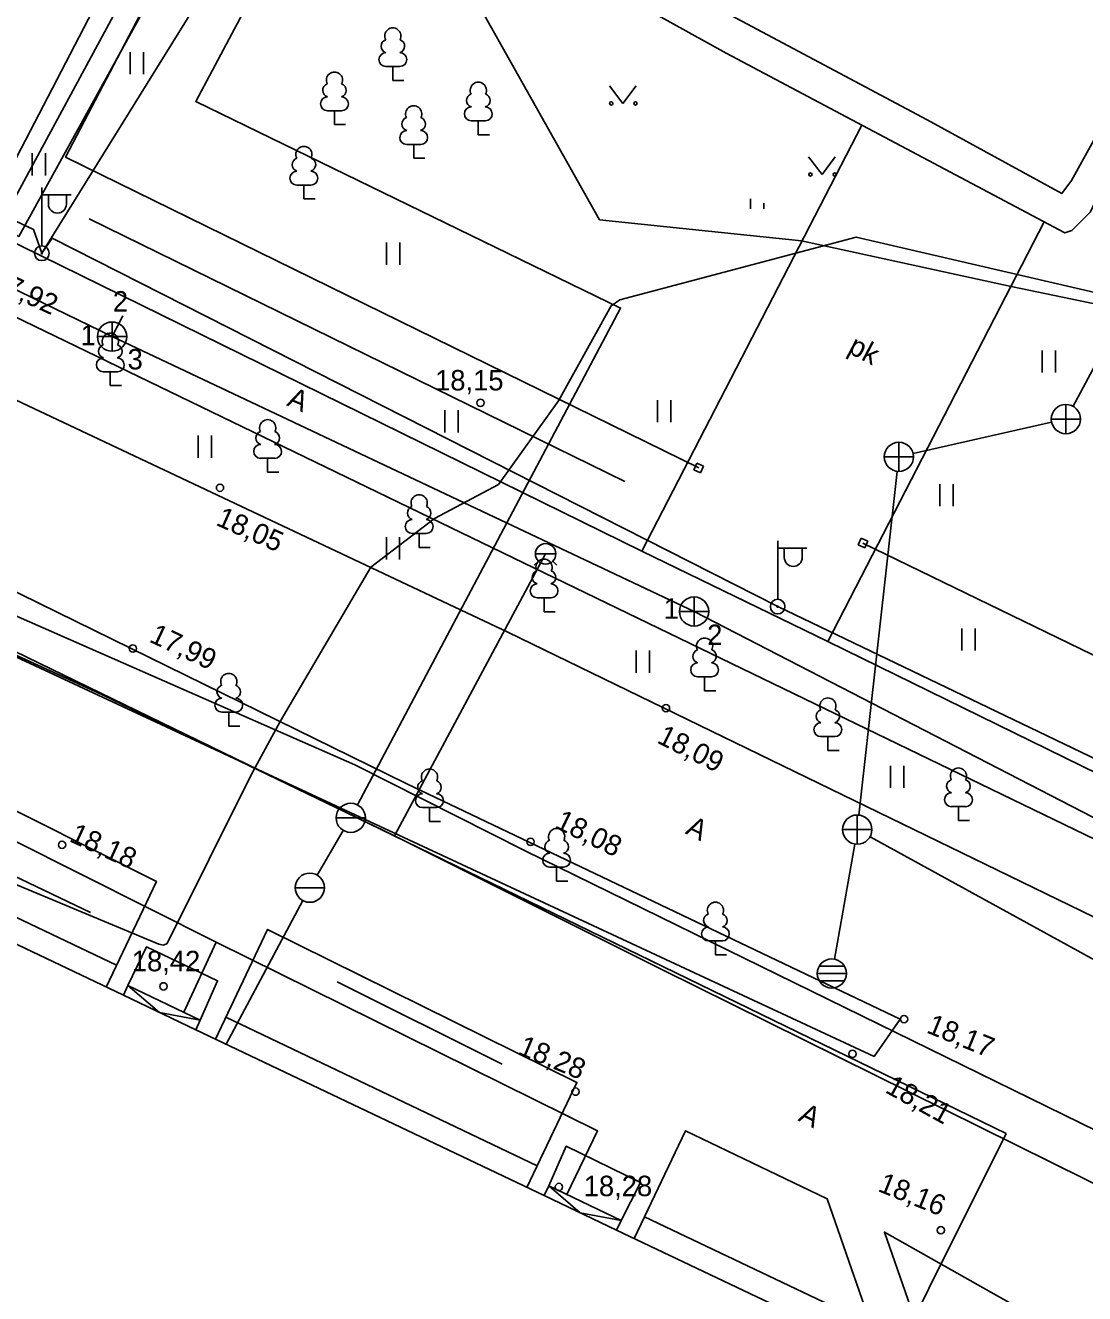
# Model space of a CAD drawing. Extents: x 713540 to 713867, y 6589774 to 6590061.
# Drawn here: x 713801.99 to 713838.21, y 6589841.34 to 6589884.71 of the extents above; entities that cross this region are included whole.
import ezdxf

# ---------------------------------------------------------------- set-up
doc = ezdxf.new("R2010")
doc.units = 0
for name, color, linetype in [('AED', 7, 'Continuous'), ('HALJASTUS', 7, 'Continuous'), ('HOONE', 7, 'Continuous'), ('HOONEDET', 7, 'Continuous'), ('KKAEV', 7, 'Continuous'), ('KORGUS', 7, 'Continuous'), ('KPKAABEL', 7, 'Continuous'), ('KTRASS', 7, 'Continuous'), ('MPKAABEL', 7, 'Continuous'), ('POST', 7, 'Continuous'), ('PUU', 7, 'Continuous'), ('SITRASS', 7, 'Continuous'), ('SKKAEV', 7, 'Continuous'), ('SKTRASS', 7, 'Continuous'), ('TEE', 7, 'Continuous'), ('TORU NR', 7, 'Continuous'), ('VKAEV', 7, 'Continuous'), ('VTRASS', 7, 'Continuous'), ('Слой 1', 7, 'Continuous')]:
    doc.layers.add(name, color=color, linetype=linetype)

msp = doc.modelspace()

# ---------------------------------------------------------------- linework, layer by layer
at = {"layer": 'AED'}
for p, q in [((713824.958, 6589869.743), (713824.853, 6589869.516)), ((713824.958, 6589869.743), (713825.185, 6589869.638)), ((713825.185, 6589869.638), (713825.08, 6589869.411)), ((713824.853, 6589869.516), (713825.08, 6589869.411)), ((713830.468, 6589866.947), (713830.573, 6589867.174)), ((713830.8, 6589867.069), (713830.573, 6589867.174)), ((713830.695, 6589866.842), (713830.8, 6589867.069)), ((713830.695, 6589866.842), (713830.468, 6589866.947))]:
    msp.add_line(p, q, dxfattribs=at)
for points in [[(713825.019, 6589869.577), (713803.37, 6589880.207), (713807.952, 6589888.966), (713812.34, 6589898.14), (713812.86, 6589897.85)], [(713830.634, 6589867.008), (713866.671, 6589849.512)]]:
    msp.add_lwpolyline(points, dxfattribs=at)
at = {"layer": 'HALJASTUS'}
for p, q in [((713805.579, 6589883.797), (713805.579, 6589883.036)), ((713806.034, 6589883.797), (713806.034, 6589883.036)), ((713821.967, 6589882.647), (713822.43, 6589882.04)), ((713822.43, 6589882.04), (713822.876, 6589882.647)), ((713802.23, 6589880.34), (713802.23, 6589879.579)), ((713802.685, 6589880.34), (713802.685, 6589879.579)), ((713828.777, 6589880.217), (713829.24, 6589879.61)), ((713829.24, 6589879.61), (713829.686, 6589880.217)), ((713826.793, 6589878.783), (713826.793, 6589878.44)), ((713827.248, 6589878.625), (713827.248, 6589878.44)), ((713814.347, 6589877.279), (713814.347, 6589876.518)), ((713814.802, 6589877.279), (713814.802, 6589876.518)), ((713836.767, 6589873.595), (713836.767, 6589872.834)), ((713837.222, 6589873.595), (713837.222, 6589872.834)), ((713823.612, 6589871.898), (713823.612, 6589871.137)), ((713824.067, 6589871.898), (713824.067, 6589871.137)), ((713816.34, 6589871.548), (713816.34, 6589870.787)), ((713816.795, 6589871.548), (713816.795, 6589870.787)), ((713807.909, 6589870.683), (713807.909, 6589869.922)), ((713808.364, 6589870.683), (713808.364, 6589869.922)), ((713833.26, 6589869.025), (713833.26, 6589868.264)), ((713833.715, 6589869.025), (713833.715, 6589868.264)), ((713814.338, 6589867.206), (713814.338, 6589866.445)), ((713814.793, 6589867.206), (713814.793, 6589866.445)), ((713834.016, 6589864.091), (713834.016, 6589863.33)), ((713834.471, 6589864.091), (713834.471, 6589863.33)), ((713822.88, 6589863.334), (713822.88, 6589862.572)), ((713823.335, 6589863.334), (713823.335, 6589862.572)), ((713831.572, 6589859.394), (713831.572, 6589858.633)), ((713832.027, 6589859.394), (713832.027, 6589858.633))]:
    msp.add_line(p, q, dxfattribs=at)
for points in [[(713822.494, 6589869.115), (713804.176, 6589878.091)], [(713795.759, 6589858.426), (713804.223, 6589854.37)], [(713812.651, 6589852), (713818.299, 6589849.187)]]:
    msp.add_lwpolyline(points, dxfattribs=at)
for centre in [(713822.029, 6589882.04), (713822.858, 6589882.04), (713828.839, 6589879.61), (713829.668, 6589879.61)]:
    msp.add_circle(centre, 0.055, dxfattribs=at)
at = {"layer": 'HOONE'}
for points in [[(713856.15, 6589912.28), (713845.91, 6589894.13), (713837.77, 6589879.4), (713837.43, 6589878.96), (713832.83, 6589881.48), (713819.45, 6589888.61), (713819.6, 6589888.94), (713824.63, 6589897.88), (713832.94, 6589912.52), (713838.13, 6589921.78), (713838.47, 6589921.97), (713856.15, 6589912.28)], [(713764.759, 6589857.466), (713770.044, 6589868.594), (713770.394, 6589868.428), (713770.304, 6589868.238), (713776.426, 6589865.322), (713776.583, 6589865.651), (713779.057, 6589864.471), (713778.901, 6589864.143), (713790.849, 6589858.452), (713791.006, 6589858.781), (713793.48, 6589857.601), (713793.324, 6589857.274), (713805.345, 6589851.548), (713805.502, 6589851.877), (713807.976, 6589850.697), (713807.82, 6589850.369), (713819.733, 6589844.695), (713819.889, 6589845.024), (713822.363, 6589843.844), (713822.207, 6589843.517), (713828.374, 6589840.579)], [(713801.581, 6589856.848), (713808.521, 6589853.357), (713821.559, 6589846.908), (713820.508, 6589844.729)], [(713807.976, 6589850.697), (713808.57, 6589852.039), (713806.132, 6589853.2), (713805.502, 6589851.877)], [(713807.415, 6589850.964), (713808.524, 6589853.356)], [(713819.889, 6589845.024), (713820.489, 6589846.381), (713823.032, 6589845.14), (713822.363, 6589843.844)]]:
    msp.add_lwpolyline(points, dxfattribs=at)
at = {"layer": 'HOONEDET'}
for p, q in [((713806.583, 6589850.959), (713805.502, 6589851.877)), ((713807.82, 6589850.369), (713805.345, 6589851.548)), ((713807.976, 6589850.697), (713806.583, 6589850.959)), ((713820.97, 6589844.106), (713819.889, 6589845.024)), ((713822.207, 6589843.517), (713819.733, 6589844.695)), ((713822.363, 6589843.844), (713820.97, 6589844.106))]:
    msp.add_line(p, q, dxfattribs=at)
for points in [[(713824.74, 6589899.73), (713818.11, 6589888.07), (713818.2, 6589888.07), (713825.96, 6589883.76), (713837.54, 6589877.61), (713837.78, 6589877.7), (713838.41, 6589878.33), (713840.01, 6589881.77)], [(713829.99, 6589840.716), (713823.163, 6589843.969)]]:
    msp.add_lwpolyline(points, dxfattribs=at)
at = {"layer": 'KKAEV'}
for p, q in [((713804.959, 6589873.565), (713804.959, 6589874.565)), ((713804.459, 6589874.065), (713805.459, 6589874.065)), ((713837.573, 6589870.746), (713837.573, 6589871.746)), ((713837.073, 6589871.246), (713838.073, 6589871.246)), ((713831.863, 6589869.456), (713831.863, 6589870.456)), ((713831.363, 6589869.956), (713832.363, 6589869.956)), ((713824.862, 6589864.167), (713824.862, 6589865.167)), ((713824.362, 6589864.667), (713825.362, 6589864.667)), ((713830.44, 6589856.708), (713830.44, 6589857.708)), ((713829.94, 6589857.208), (713830.94, 6589857.208))]:
    msp.add_line(p, q, dxfattribs=at)
for centre in [(713804.959, 6589874.065), (713837.573, 6589871.246), (713831.863, 6589869.956), (713824.862, 6589864.667), (713830.44, 6589857.208)]:
    msp.add_circle(centre, 0.5, dxfattribs=at)
at = {"layer": 'KORGUS'}
for centre in [(713817.56, 6589871.8), (713808.65, 6589868.9), (713805.67, 6589863.4), (713823.9, 6589861.36), (713803.25, 6589856.69), (713819.27, 6589856.79), (713806.72, 6589851.85), (713832.04, 6589850.73), (713830.28, 6589849.54), (713820.81, 6589848.25), (713820.24, 6589844.99), (713833.3, 6589843.51)]:
    msp.add_circle(centre, 0.125, dxfattribs=at)
at = {"layer": 'KPKAABEL'}
msp.add_lwpolyline([(713798.55, 6589856.631), (713806.554, 6589853.297), (713806.72, 6589853.255), (713806.842, 6589853.316), (713809.704, 6589859.058), (713810.708, 6589860.907), (713813.804, 6589866.184), (713815.987, 6589867.852), (713818.176, 6589869.014), (713820.222, 6589871.87), (713822.023, 6589875.121), (713822.324, 6589875.322), (713830.403, 6589877.468), (713854.54, 6589871.87), (713866.671, 6589869.213)], dxfattribs=at)
at = {"layer": 'KTRASS'}
for p, q in [((713795.486, 6589878.673), (713804.959, 6589874.065)), ((713804.959, 6589874.065), (713805.323, 6589874.782)), ((713804.959, 6589874.065), (713824.862, 6589864.667)), ((713824.862, 6589864.667), (713862.109, 6589845.451))]:
    msp.add_line(p, q, dxfattribs=at)
at = {"layer": 'MPKAABEL'}
for points in [[(713694.011, 6589938.961), (713720.287, 6589922.261), (713729.28, 6589921.07), (713735.396, 6589911.684), (713736.91, 6589909.36), (713749.796, 6589902.534), (713750.086, 6589902.788), (713778.179, 6589889.116), (713778.272, 6589888.686), (713778.52, 6589888.95), (713802.27, 6589877.73), (713802.558, 6589876.915), (713802.91, 6589877.43), (713827.719, 6589864.835), (713849.02, 6589854.61), (713849.184, 6589854.353), (713849.72, 6589854.26), (713866.671, 6589846.028)], [(713866.671, 6589870.418), (713866.215, 6589870.524), (713859.51, 6589871.028), (713844.257, 6589874.001), (713835.7, 6589875.783), (713828.536, 6589877.344), (713821.631, 6589878.061), (713816.967, 6589886.362), (713816.359, 6589889.318), (713817.008, 6589896.566), (713814.12, 6589901.017)], [(713802.558, 6589876.915), (713807.651, 6589885.123), (713809.238, 6589888.304)]]:
    msp.add_lwpolyline(points, dxfattribs=at)
at = {"layer": 'POST'}
for p, q in [((713802.558, 6589877.165), (713802.558, 6589879.165)), ((713802.558, 6589878.915), (713803.558, 6589878.915)), ((713802.785, 6589878.594), (713802.785, 6589878.915)), ((713803.398, 6589878.594), (713803.398, 6589878.915)), ((713827.719, 6589865.085), (713827.719, 6589867.085)), ((713827.719, 6589866.835), (713828.719, 6589866.835)), ((713827.946, 6589866.514), (713827.946, 6589866.835)), ((713828.558, 6589866.514), (713828.558, 6589866.835))]:
    msp.add_line(p, q, dxfattribs=at)
for centre, radius in [((713802.558, 6589876.915), 0.25), ((713802.558, 6589876.915), 0.0234), ((713827.719, 6589864.835), 0.25), ((713827.719, 6589864.835), 0.0234)]:
    msp.add_circle(centre, radius, dxfattribs=at)
for centre in [(713803.091, 6589878.594), (713828.252, 6589866.514)]:
    msp.add_arc(centre, 0.306, 180, 0, dxfattribs=at)
at = {"layer": 'PUU'}
for p, q in [((713814.801, 6589883.301), (713814.321, 6589883.301)), ((713814.561, 6589882.826), (713814.561, 6589883.301)), ((713814.941, 6589882.826), (713814.561, 6589882.826)), ((713812.804, 6589881.79), (713812.324, 6589881.79)), ((713812.564, 6589881.315), (713812.564, 6589881.79)), ((713812.944, 6589881.315), (713812.564, 6589881.315)), ((713817.723, 6589881.444), (713817.243, 6589881.444)), ((713817.483, 6589880.969), (713817.483, 6589881.444)), ((713817.863, 6589880.969), (713817.483, 6589880.969)), ((713815.513, 6589880.638), (713815.033, 6589880.638)), ((713815.273, 6589880.163), (713815.273, 6589880.638)), ((713815.653, 6589880.163), (713815.273, 6589880.163)), ((713811.759, 6589879.247), (713811.279, 6589879.247)), ((713811.519, 6589878.772), (713811.519, 6589879.247)), ((713811.899, 6589878.772), (713811.519, 6589878.772)), ((713805.14, 6589872.865), (713804.66, 6589872.865)), ((713804.9, 6589872.39), (713804.9, 6589872.865)), ((713805.28, 6589872.39), (713804.9, 6589872.39)), ((713810.52, 6589869.905), (713810.04, 6589869.905)), ((713810.28, 6589869.43), (713810.28, 6589869.905)), ((713810.66, 6589869.43), (713810.28, 6589869.43)), ((713815.7, 6589867.335), (713815.22, 6589867.335)), ((713815.46, 6589866.86), (713815.46, 6589867.335)), ((713815.84, 6589866.86), (713815.46, 6589866.86)), ((713819.97, 6589865.135), (713819.49, 6589865.135)), ((713819.73, 6589864.66), (713819.73, 6589865.135)), ((713820.11, 6589864.66), (713819.73, 6589864.66)), ((713825.46, 6589862.435), (713824.98, 6589862.435)), ((713825.22, 6589861.96), (713825.22, 6589862.435)), ((713825.6, 6589861.96), (713825.22, 6589861.96)), ((713809.19, 6589861.225), (713808.71, 6589861.225)), ((713808.95, 6589860.75), (713808.95, 6589861.225)), ((713809.33, 6589860.75), (713808.95, 6589860.75)), ((713829.676, 6589860.39), (713829.196, 6589860.39)), ((713829.436, 6589859.915), (713829.436, 6589860.39)), ((713829.816, 6589859.915), (713829.436, 6589859.915)), ((713816.053, 6589857.961), (713815.573, 6589857.961)), ((713815.813, 6589857.486), (713815.813, 6589857.961)), ((713834.14, 6589857.995), (713833.66, 6589857.995)), ((713833.9, 6589857.52), (713833.9, 6589857.995)), ((713816.193, 6589857.486), (713815.813, 6589857.486)), ((713834.28, 6589857.52), (713833.9, 6589857.52)), ((713820.4, 6589855.925), (713819.92, 6589855.925)), ((713820.16, 6589855.45), (713820.16, 6589855.925)), ((713820.54, 6589855.45), (713820.16, 6589855.45)), ((713825.83, 6589853.405), (713825.35, 6589853.405)), ((713825.59, 6589852.93), (713825.59, 6589853.405)), ((713825.97, 6589852.93), (713825.59, 6589852.93))]:
    msp.add_line(p, q, dxfattribs=at)
for centre, radius, start, end in [((713814.561, 6589884.346), 0.277, 332.5799, 207.4201), ((713814.391, 6589883.998), 0.233, 109.0217, 253.1415), ((713814.731, 6589883.998), 0.233, 286.8508, 70.9859), ((713814.324, 6589883.538), 0.238, 90.0016, 269.3953), ((713814.799, 6589883.538), 0.238, 270.6047, 89.9984), ((713812.564, 6589882.835), 0.277, 332.5799, 207.4201), ((713812.394, 6589882.487), 0.233, 109.0217, 253.1415), ((713812.734, 6589882.487), 0.233, 286.8508, 70.9859), ((713817.483, 6589882.489), 0.277, 332.5799, 207.4201), ((713812.327, 6589882.027), 0.238, 90.0016, 269.3953), ((713812.802, 6589882.027), 0.238, 270.6047, 89.9984), ((713817.313, 6589882.142), 0.233, 109.0217, 253.1415), ((713817.653, 6589882.142), 0.233, 286.8508, 70.9859), ((713815.273, 6589881.683), 0.277, 332.5799, 207.4201), ((713817.245, 6589881.682), 0.238, 90.0016, 269.3953), ((713817.72, 6589881.682), 0.238, 270.6047, 89.9984), ((713815.103, 6589881.336), 0.233, 109.0217, 253.1415), ((713815.444, 6589881.336), 0.233, 286.8508, 70.9859), ((713815.036, 6589880.876), 0.238, 90.0016, 269.3953), ((713815.511, 6589880.876), 0.238, 270.6047, 89.9984), ((713811.519, 6589880.292), 0.277, 332.5799, 207.4201), ((713811.349, 6589879.944), 0.233, 109.0217, 253.1415), ((713811.689, 6589879.944), 0.233, 286.8508, 70.9859), ((713811.281, 6589879.484), 0.238, 90.0016, 269.3953), ((713811.756, 6589879.484), 0.238, 270.6047, 89.9984), ((713804.9, 6589873.91), 0.277, 332.5799, 207.4201), ((713804.73, 6589873.563), 0.233, 109.0217, 253.1415), ((713805.07, 6589873.563), 0.233, 286.8508, 70.9859), ((713804.663, 6589873.102), 0.238, 90.0016, 269.3953), ((713805.137, 6589873.102), 0.238, 270.6047, 89.9984), ((713810.28, 6589870.95), 0.277, 332.5799, 207.4201), ((713810.11, 6589870.603), 0.233, 109.0217, 253.1415), ((713810.45, 6589870.603), 0.233, 286.8508, 70.9859), ((713810.043, 6589870.142), 0.238, 90.0016, 269.3953), ((713810.517, 6589870.142), 0.238, 270.6047, 89.9984), ((713815.46, 6589868.38), 0.277, 332.5799, 207.4201), ((713815.29, 6589868.033), 0.233, 109.0217, 253.1415), ((713815.63, 6589868.033), 0.233, 286.8508, 70.9859), ((713815.223, 6589867.572), 0.238, 90.0016, 269.3953), ((713815.697, 6589867.572), 0.238, 270.6047, 89.9984), ((713819.73, 6589866.18), 0.277, 332.5799, 207.4201), ((713819.56, 6589865.833), 0.233, 109.0217, 253.1415), ((713819.9, 6589865.833), 0.233, 286.8508, 70.9859), ((713819.493, 6589865.372), 0.238, 90.0016, 269.3953), ((713819.967, 6589865.372), 0.238, 270.6047, 89.9984), ((713825.22, 6589863.48), 0.277, 332.5799, 207.4201), ((713825.05, 6589863.133), 0.233, 109.0217, 253.1415), ((713825.39, 6589863.133), 0.233, 286.8508, 70.9859), ((713824.983, 6589862.672), 0.238, 90.0016, 269.3953), ((713825.457, 6589862.672), 0.238, 270.6047, 89.9984), ((713808.95, 6589862.27), 0.277, 332.5799, 207.4201), ((713808.78, 6589861.923), 0.233, 109.0217, 253.1415), ((713809.12, 6589861.923), 0.233, 286.8508, 70.9859), ((713808.713, 6589861.462), 0.238, 90.0016, 269.3953), ((713809.187, 6589861.462), 0.238, 270.6047, 89.9984), ((713829.436, 6589861.435), 0.277, 332.5799, 207.4201), ((713829.266, 6589861.088), 0.233, 109.0217, 253.1415), ((713829.606, 6589861.088), 0.233, 286.8508, 70.9859), ((713829.198, 6589860.628), 0.238, 90.0016, 269.3953), ((713829.673, 6589860.628), 0.238, 270.6047, 89.9984), ((713815.813, 6589859.006), 0.277, 332.5799, 207.4201), ((713833.9, 6589859.04), 0.277, 332.5799, 207.4201), ((713815.643, 6589858.658), 0.233, 109.0217, 253.1415), ((713815.983, 6589858.658), 0.233, 286.8508, 70.9859), ((713833.73, 6589858.693), 0.233, 109.0217, 253.1415), ((713834.07, 6589858.693), 0.233, 286.8508, 70.9859), ((713815.576, 6589858.198), 0.238, 90.0016, 269.3953), ((713816.051, 6589858.198), 0.238, 270.6047, 89.9984), ((713833.663, 6589858.232), 0.238, 90.0016, 269.3953), ((713834.137, 6589858.232), 0.238, 270.6047, 89.9984), ((713820.16, 6589856.97), 0.277, 332.5799, 207.4201), ((713819.99, 6589856.623), 0.233, 109.0217, 253.1415), ((713820.33, 6589856.623), 0.233, 286.8508, 70.9859), ((713819.923, 6589856.162), 0.238, 90.0016, 269.3953), ((713820.397, 6589856.162), 0.238, 270.6047, 89.9984), ((713825.59, 6589854.45), 0.277, 332.5799, 207.4201), ((713825.42, 6589854.103), 0.233, 109.0217, 253.1415), ((713825.76, 6589854.103), 0.233, 286.8508, 70.9859), ((713825.353, 6589853.642), 0.238, 90.0016, 269.3953), ((713825.827, 6589853.642), 0.238, 270.6047, 89.9984)]:
    msp.add_arc(centre, radius, start, end, dxfattribs=at)
at = {"layer": 'SITRASS'}
msp.add_lwpolyline([(713866.671, 6589832.925), (713865.57, 6589833.47), (713840.95, 6589845.77), (713819.08, 6589856.48), (713813.26, 6589859.42), (713789.96, 6589869.66), (713773.99, 6589876.98), (713762.77, 6589881.28), (713755.5, 6589884.39), (713750.27, 6589886.88), (713741.03, 6589891.38), (713722.91, 6589899.77), (713722.841, 6589899.769)], dxfattribs=at)
at = {"layer": 'SKKAEV'}
for p, q in [((713829.07, 6589852.29), (713830.07, 6589852.29)), ((713830, 6589852.54), (713829.14, 6589852.54)), ((713830, 6589852.04), (713829.14, 6589852.04))]:
    msp.add_line(p, q, dxfattribs=at)
msp.add_circle((713829.57, 6589852.29), 0.5, dxfattribs=at)
at = {"layer": 'SKTRASS'}
for points in [[(713837.821, 6589871.685), (713858.87, 6589910.99), (713860.1, 6589914.37), (713852.11, 6589921.91), (713866.671, 6589948.059)], [(713832.35, 6589870.066), (713837.085, 6589871.136)], [(713830.495, 6589857.705), (713831.807, 6589869.459)], [(713829.657, 6589852.782), (713830.353, 6589856.715)], [(713830.878, 6589856.967), (713854.512, 6589843.991)]]:
    msp.add_lwpolyline(points, dxfattribs=at)
at = {"layer": 'TEE'}
for points in [[(713806.743, 6589889.925), (713800.462, 6589877.845), (713823.07, 6589866.735), (713829.432, 6589863.637), (713847.947, 6589854.565), (713866.671, 6589845.438)], [(713823.07, 6589866.735), (713830.597, 6589881.297)], [(713773.008, 6589877.094), (713773.059, 6589879.061), (713796.776, 6589867.731), (713815.015, 6589858.783), (713831.91, 6589850.731), (713831.016, 6589849.454), (713794.188, 6589866.59), (713773.008, 6589877.094)], [(713836.83, 6589877.987), (713829.432, 6589863.637)], [(713866.671, 6589843.226), (713847.121, 6589852.734), (713799.452, 6589875.805)], [(713866.671, 6589840.594), (713842.202, 6589852.438), (713818.495, 6589863.956), (713799.225, 6589873.05)], [(713804.759, 6589851.827), (713806.477, 6589855.434), (713795.699, 6589860.854), (713793.87, 6589857.014)], [(713794.225, 6589857.76), (713805.113, 6589852.571)], [(713819.146, 6589844.975), (713820.856, 6589848.564), (713810.279, 6589853.795), (713808.495, 6589850.048)], [(713808.848, 6589850.791), (713819.499, 6589845.715)], [(713822.811, 6589843.229), (713824.566, 6589846.913), (713829.407, 6589844.586), (713832.457, 6589835.83), (713833.78, 6589830.86), (713834.06, 6589830.04), (713831.78, 6589825.42), (713813.12, 6589786.46)], [(713838.195, 6589839.595), (713831.369, 6589843.448), (713835.008, 6589833.003), (713838.195, 6589839.595)]]:
    msp.add_lwpolyline(points, dxfattribs=at)
at = {"layer": 'VKAEV'}
for p, q in [((713819.434, 6589866.637), (713820.134, 6589866.637)), ((713819.537, 6589866.389), (713819.397, 6589866.25)), ((713820.032, 6589866.389), (713820.171, 6589866.25)), ((713812.62, 6589857.612), (713813.62, 6589857.612)), ((713811.221, 6589855.224), (713812.221, 6589855.224))]:
    msp.add_line(p, q, dxfattribs=at)
for centre, radius in [((713819.784, 6589866.637), 0.35), ((713813.12, 6589857.612), 0.5), ((713811.721, 6589855.224), 0.5)]:
    msp.add_circle(centre, radius, dxfattribs=at)
at = {"layer": 'VTRASS'}
for points in [[(713721.093, 6589902.329), (713733.497, 6589895.603), (713741.572, 6589891.713), (713756.471, 6589884.465), (713765.548, 6589879.995), (713782.769, 6589871.45), (713795.373, 6589866.054), (713804.634, 6589861.821), (713814.617, 6589856.993), (713823.754, 6589852.427), (713844.326, 6589842.238), (713851.629, 6589837.843), (713859.935, 6589832.639), (713860.708, 6589832.099), (713861.139, 6589831.812)], [(713795.373, 6589866.054), (713800.446, 6589876.335), (713800.548, 6589876.538), (713801.033, 6589877.706), (713806.752, 6589888.284), (713812.598, 6589899.578)], [(713815.579, 6589896.685), (713807.82, 6589882.11), (713822.35, 6589875.04), (713813.354, 6589858.054)], [(713814.617, 6589856.993), (713819.784, 6589866.637)], [(713811.974, 6589855.656), (713812.867, 6589857.181)], [(713808.859, 6589849.875), (713811.485, 6589854.783)]]:
    msp.add_lwpolyline(points, dxfattribs=at)
at = {"layer": 'Слой 1'}
for points in [[(713801.77, 6589877.49), (713765.63, 6589894.55), (713785.68, 6589930.05), (713821.49, 6589913.26)], [(713835.53, 6589846.82), (713832.89, 6589841.52), (713822.02, 6589819.7), (713754.51, 6589852.01), (713765.74, 6589876.63), (713767.28, 6589880.01)]]:
    msp.add_lwpolyline(points, close=True, dxfattribs=at)

# ---------------------------------------------------------------- texts
at = {"layer": 'KORGUS'}
for s, rotation, p in [('17,92', 335.3994, (713800.771, 6589875.768)), ('18,05', 336.0082, (713808.475, 6589867.637)), ('17,99', 334.7528, (713806.196, 6589863.648)), ('18,09', 333.1916, (713823.553, 6589860.2)), ('18,08', 333.7782, (713820.065, 6589857.293)), ('18,18', 335.423, (713803.462, 6589856.822)), ('18,17', 337.8399, (713832.773, 6589850.281)), ('18,28', 337.324, (713818.802, 6589849.551)), ('18,21', 331.1614, (713831.358, 6589848.242)), ('18,16', 338.1221, (713831.111, 6589844.858))]:
    msp.add_text(s, height=0.7, rotation=rotation, dxfattribs=at).set_placement(p)
for s, p in [('18,15', (713816.003, 6589872.225)), ('18,42', (713805.633, 6589852.365)), ('18,28', (713821.086, 6589844.675))]:
    msp.add_text(s, height=0.7, dxfattribs=at).set_placement(p)
at = {"layer": 'TEE'}
for s, rotation, p in [('pk', 332.2303, (713830.083, 6589873.536)), ('A', 336.953, (713810.902, 6589871.719)), ('A', 333.4463, (713824.531, 6589857.085)), ('A', 333.4463, (713828.39, 6589847.27))]:
    msp.add_text(s, height=0.7, rotation=rotation, dxfattribs=at).set_placement(p)
at = {"layer": 'TORU NR'}
for s, p in [('2', (713804.987, 6589874.922)), ('1', (713803.882, 6589873.767)), ('3', (713805.491, 6589872.944)), ('1', (713823.822, 6589864.418)), ('2', (713825.308, 6589863.521))]:
    msp.add_text(s, height=0.7, dxfattribs=at).set_placement(p)

doc.saveas('drawing.dxf')
